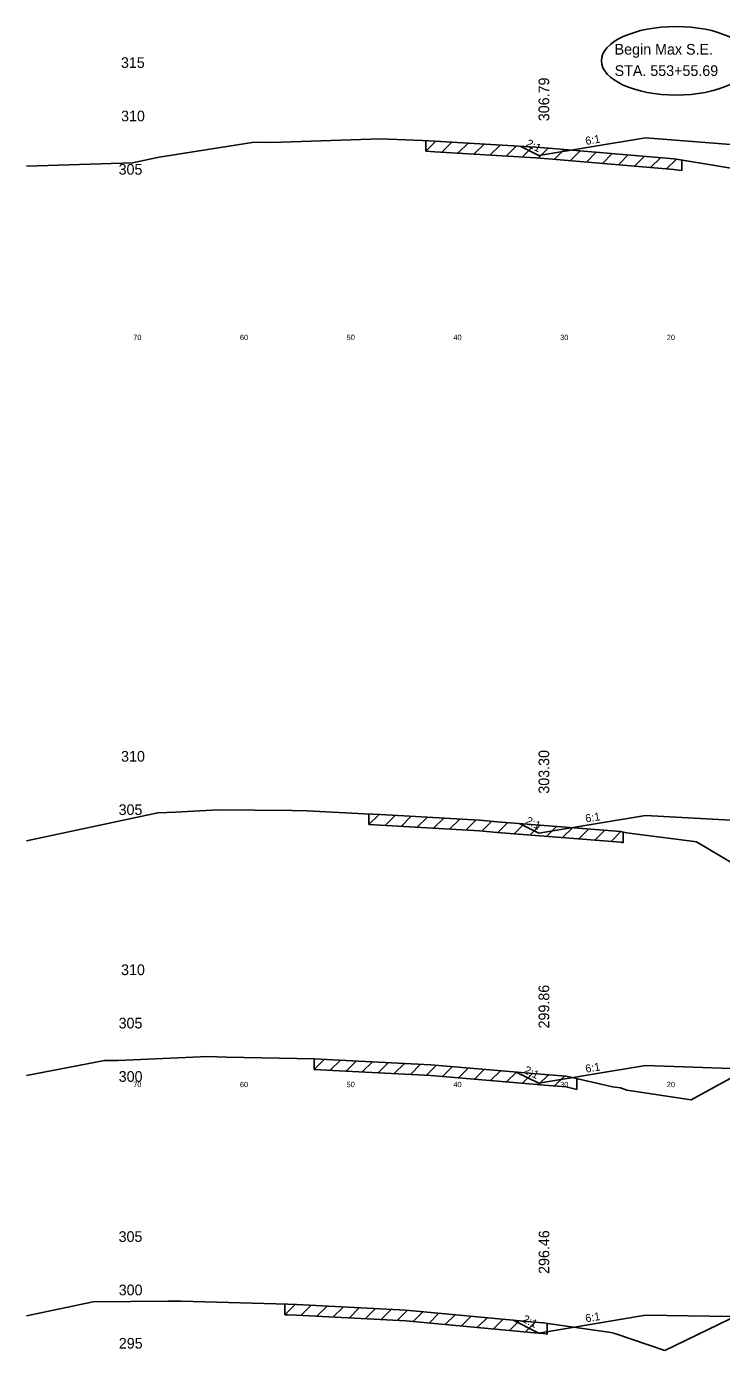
# Model space of a CAD drawing. Extents: x 1000 to 1162, y 999 to 8520.
# Drawn here: x 1000 to 1065.1, y 7344.8 to 7468.9 of the extents above; entities that cross this region are included whole.
import ezdxf

# ---------------------------------------------------------------- set-up
doc = ezdxf.new("R2010")
doc.units = 0
for name, color, linetype in [('Level 11', 7, 'Continuous'), ('Level 20', 7, 'Continuous'), ('Level 32', 7, 'Continuous'), ('Level 33', 7, 'Continuous'), ('Level 56', 7, 'Continuous'), ('Level 6', 7, 'Continuous'), ('Level 60', 7, 'Continuous'), ('Level 61', 7, 'Continuous'), ('Level 7', 7, 'Continuous')]:
    doc.layers.add(name, color=color, linetype=linetype)

msp = doc.modelspace()

# ---------------------------------------------------------------- linework, layer by layer
at = {"layer": 'Level 20'}
msp.add_ellipse((1060.87, 7465.67), major_axis=(7, 0), ratio=0.458988, dxfattribs=at)
at = {"layer": 'Level 6'}
for p, q in [((1058, 7458.46), (1066, 7457.84)), ((1058, 7394.97), (1066, 7394.51)), ((1058, 7371.53), (1066, 7371.24)), ((1058, 7348.13), (1066, 7348.01))]:
    msp.add_line(p, q, dxfattribs=at)
at = {"layer": 'Level 60'}
for p, q in [((1012.43, 7456.65), (1021.15, 7458.01)), ((1021.15, 7458.01), (1021.81, 7458.04)), ((1021.81, 7458.04), (1022.93, 7458.03)), ((1022.93, 7458.03), (1033.2, 7458.36)), ((1033.2, 7458.36), (1033.93, 7458.32)), ((1033.93, 7458.32), (1037.11, 7458.21)), ((1037.11, 7458.21), (1038.27, 7458.14)), ((1038.27, 7458.14), (1047.73, 7457.57)), ((1047.73, 7457.57), (1048.9, 7457.47)), ((1048.9, 7457.47), (1060.65, 7456.49)), ((1009.92, 7456.12), (1012.43, 7456.65)), ((1060.65, 7456.49), (1061.1, 7456.43)), ((1061.1, 7456.43), (1067.89, 7455.29)), ((1000, 7455.81), (1009.92, 7456.12)), ((1013.96, 7395.28), (1017.94, 7395.49)), ((1017.94, 7395.49), (1024.86, 7395.43)), ((1024.86, 7395.43), (1026.3, 7395.4)), ((1026.3, 7395.4), (1031.68, 7395.12)), ((1000, 7392.58), (1012.31, 7395.21)), ((1012.31, 7395.21), (1013.96, 7395.28)), ((1031.68, 7395.12), (1033.16, 7395.05)), ((1033.16, 7395.05), (1042.45, 7394.51)), ((1042.45, 7394.51), (1044.09, 7394.37)), ((1044.09, 7394.37), (1055.69, 7393.45)), ((1055.69, 7393.45), (1056.23, 7393.33)), ((1056.23, 7393.33), (1062.1, 7392.58)), ((1062.1, 7392.58), (1062.79, 7392.48)), ((1062.79, 7392.48), (1066.26, 7390.42)), ((1062.27, 7368.32), (1071.04, 7373.12)), ((1000, 7370.6), (1007.31, 7371.99)), ((1007.31, 7371.99), (1008.59, 7372.01)), ((1008.59, 7372.01), (1016.98, 7372.37)), ((1016.98, 7372.37), (1018.73, 7372.32)), ((1018.73, 7372.32), (1027, 7372.16)), ((1027, 7372.16), (1028.72, 7372.07)), ((1028.72, 7372.07), (1037.89, 7371.59)), ((1037.89, 7371.59), (1048.95, 7370.67)), ((1048.95, 7370.67), (1050.56, 7370.52)), ((1050.56, 7370.52), (1054.92, 7369.54)), ((1054.92, 7369.54), (1055.67, 7369.43)), ((1055.67, 7369.43), (1056.26, 7369.22)), ((1056.26, 7369.22), (1062.27, 7368.32)), ((1006.25, 7349.38), (1013.3, 7349.45)), ((1013.3, 7349.45), (1013.71, 7349.46)), ((1013.71, 7349.46), (1014.48, 7349.46)), ((1014.48, 7349.46), (1024.5, 7349.17)), ((1000, 7348.07), (1006.25, 7349.38)), ((1024.5, 7349.17), (1025.31, 7349.13)), ((1025.31, 7349.13), (1035.54, 7348.59)), ((1035.54, 7348.59), (1047.6, 7347.49)), ((1059.81, 7344.82), (1069.27, 7349.42)), ((1047.6, 7347.49), (1048.43, 7347.42)), ((1048.43, 7347.42), (1048.85, 7347.36)), ((1048.85, 7347.36), (1054.76, 7346.51)), ((1054.76, 7346.51), (1055.12, 7346.43)), ((1055.12, 7346.43), (1059.81, 7344.82))]:
    msp.add_line(p, q, dxfattribs=at)
at = {"layer": 'Level 61'}
for p, q in [((1037.42, 7458.19), (1037.42, 7457.19)), ((1038.36, 7458.14), (1037.42, 7457.19)), ((1039.87, 7458.05), (1038.92, 7457.1)), ((1041.37, 7457.96), (1040.42, 7457.01)), ((1042.87, 7457.86), (1041.93, 7456.92)), ((1044.38, 7457.77), (1043.43, 7456.83)), ((1045.88, 7457.68), (1044.94, 7456.74)), ((1047.39, 7457.59), (1046.44, 7456.65)), ((1048.87, 7457.48), (1047.95, 7456.55)), ((1037.42, 7457.19), (1038.27, 7457.14)), ((1038.27, 7457.14), (1047.73, 7456.57)), ((1047.73, 7456.57), (1048.9, 7456.47)), ((1048.9, 7456.47), (1060.65, 7455.49)), ((1050.38, 7457.35), (1049.45, 7456.43)), ((1051.88, 7457.22), (1050.95, 7456.3)), ((1053.38, 7457.1), (1052.46, 7456.18)), ((1054.89, 7456.97), (1053.96, 7456.05)), ((1056.39, 7456.85), (1055.47, 7455.92)), ((1057.9, 7456.72), (1056.97, 7455.8)), ((1059.4, 7456.59), (1058.48, 7455.67)), ((1060.9, 7456.46), (1059.98, 7455.55)), ((1061.4, 7455.38), (1061.4, 7456.38)), ((1060.65, 7455.49), (1061.1, 7455.43)), ((1061.1, 7455.43), (1061.4, 7455.38)), ((1032.08, 7395.1), (1032.08, 7394.1)), ((1033.04, 7395.05), (1032.08, 7394.1)), ((1034.55, 7394.97), (1033.6, 7394.02)), ((1036.06, 7394.88), (1035.11, 7393.93)), ((1037.57, 7394.79), (1036.62, 7393.85)), ((1039.09, 7394.7), (1038.13, 7393.76)), ((1040.6, 7394.62), (1039.64, 7393.67)), ((1042.11, 7394.53), (1041.16, 7393.59)), ((1043.6, 7394.41), (1042.67, 7393.49)), ((1045.11, 7394.29), (1044.18, 7393.37)), ((1046.63, 7394.17), (1045.69, 7393.25)), ((1032.08, 7394.1), (1033.16, 7394.05)), ((1033.16, 7394.05), (1042.45, 7393.51)), ((1042.45, 7393.51), (1044.09, 7393.37)), ((1044.09, 7393.37), (1055.69, 7392.45)), ((1048.14, 7394.05), (1047.21, 7393.13)), ((1049.65, 7393.93), (1048.72, 7393)), ((1051.16, 7393.81), (1050.23, 7392.88)), ((1052.68, 7393.69), (1051.74, 7392.76)), ((1054.19, 7393.57), (1053.26, 7392.64)), ((1055.7, 7393.45), (1054.77, 7392.52)), ((1055.9, 7392.4), (1055.9, 7393.4)), ((1055.69, 7392.45), (1055.9, 7392.4)), ((1026.95, 7372.16), (1026.95, 7371.16)), ((1027.91, 7372.12), (1026.95, 7371.16)), ((1029.41, 7372.04), (1028.45, 7371.09)), ((1030.91, 7371.96), (1029.96, 7371.01)), ((1032.41, 7371.88), (1031.46, 7370.93)), ((1033.91, 7371.8), (1032.96, 7370.85)), ((1026.95, 7371.16), (1027, 7371.16)), ((1027, 7371.16), (1028.72, 7371.07)), ((1028.72, 7371.07), (1037.89, 7370.59)), ((1035.41, 7371.72), (1034.46, 7370.77)), ((1036.92, 7371.64), (1035.97, 7370.69)), ((1038.4, 7371.54), (1037.47, 7370.61)), ((1037.89, 7370.59), (1048.95, 7369.67)), ((1039.89, 7371.42), (1038.97, 7370.5)), ((1041.4, 7371.29), (1040.47, 7370.37)), ((1042.9, 7371.17), (1041.97, 7370.25)), ((1044.4, 7371.04), (1043.48, 7370.12)), ((1045.9, 7370.92), (1044.98, 7370)), ((1047.41, 7370.79), (1046.48, 7369.87)), ((1048.91, 7370.67), (1047.98, 7369.75)), ((1048.95, 7369.67), (1050.56, 7369.52)), ((1050.4, 7370.53), (1049.49, 7369.62)), ((1050.56, 7369.52), (1051.56, 7369.29)), ((1051.56, 7369.29), (1051.56, 7370.29)), ((1024.22, 7349.17), (1024.22, 7348.17)), ((1025.18, 7349.14), (1024.22, 7348.17)), ((1026.67, 7349.06), (1025.72, 7348.11)), ((1028.17, 7348.98), (1027.22, 7348.03)), ((1029.68, 7348.9), (1028.72, 7347.95)), ((1031.18, 7348.82), (1030.23, 7347.87)), ((1032.68, 7348.74), (1031.73, 7347.79)), ((1034.18, 7348.67), (1033.23, 7347.72)), ((1035.68, 7348.58), (1034.73, 7347.64)), ((1037.15, 7348.45), (1036.24, 7347.53)), ((1038.65, 7348.31), (1037.74, 7347.39)), ((1024.22, 7348.17), (1024.5, 7348.17)), ((1024.5, 7348.17), (1025.31, 7348.13)), ((1025.31, 7348.13), (1035.54, 7347.59)), ((1035.54, 7347.59), (1047.6, 7346.49)), ((1040.16, 7348.17), (1039.24, 7347.25)), ((1041.66, 7348.03), (1040.74, 7347.12)), ((1043.16, 7347.89), (1042.24, 7346.98)), ((1044.66, 7347.76), (1043.75, 7346.84)), ((1046.17, 7347.62), (1045.25, 7346.7)), ((1047.67, 7347.48), (1046.75, 7346.56)), ((1048.78, 7346.37), (1048.78, 7347.37)), ((1047.6, 7346.49), (1048.43, 7346.42)), ((1048.43, 7346.42), (1048.78, 7346.37))]:
    msp.add_line(p, q, dxfattribs=at)
at = {"layer": 'Level 7'}
for p, q in [((1046.26, 7457.66), (1048, 7456.79)), ((1048, 7456.79), (1058, 7458.46)), ((1046.19, 7394.21), (1048, 7393.3)), ((1048, 7393.3), (1058, 7394.97)), ((1045.87, 7370.92), (1048, 7369.86)), ((1048, 7369.86), (1058, 7371.53)), ((1045.59, 7347.67), (1048, 7346.46)), ((1048, 7346.46), (1058, 7348.13))]:
    msp.add_line(p, q, dxfattribs=at)

# ---------------------------------------------------------------- texts
at = {"layer": 'Level 11'}
for s, p in [(' 315', (1008.48, 7465)), (' 310', (1008.49, 7460)), (' 305', (1008.26, 7455)), (' 310', (1008.49, 7400)), (' 305', (1008.26, 7395)), (' 310', (1008.49, 7380)), (' 305', (1008.26, 7375)), (' 300', (1008.27, 7370)), (' 305', (1008.26, 7355)), (' 300', (1008.27, 7350)), (' 295', (1008.28, 7345))]:
    msp.add_text(s, height=1, dxfattribs=at).set_placement(p)
at = {"layer": 'Level 20'}
for s, p in [('Begin Max S.E.', (1055.11, 7466.25)), ('STA. 553+55.69', (1055.11, 7464.25))]:
    msp.add_text(s, height=1, dxfattribs=at).set_placement(p)
at = {"layer": 'Level 32'}
for s, rotation, p in [('6:1', 9.4623, (1052.43, 7457.78)), ('2:1', 333.435, (1046.74, 7457.7)), ('2:1', 333.435, (1046.7, 7394.23)), ('6:1', 9.4623, (1052.43, 7394.29)), ('6:1', 9.4623, (1052.43, 7370.85)), ('2:1', 333.435, (1046.54, 7370.87)), ('6:1', 9.4623, (1052.43, 7347.46)), ('2:1', 333.435, (1046.4, 7347.54))]:
    msp.add_text(s, height=0.75, rotation=rotation, dxfattribs=at).set_placement(p)
at = {"layer": 'Level 33'}
for s, p in [('306.79', (1048.98, 7460.01)), ('303.30', (1048.98, 7397)), ('299.86', (1048.98, 7375)), ('296.46', (1048.99, 7352))]:
    msp.add_text(s, height=1, rotation=90, dxfattribs=at).set_placement(p)
at = {"layer": 'Level 56'}
for s, p in [('70', (1010, 7439.5)), ('60', (1020, 7439.5)), ('50', (1030, 7439.5)), ('40', (1040, 7439.5)), ('30', (1050, 7439.5)), ('20', (1060, 7439.5)), ('70', (1010, 7369.5)), ('60', (1020, 7369.5)), ('50', (1030, 7369.5)), ('40', (1040, 7369.5)), ('30', (1050, 7369.5)), ('20', (1060, 7369.5))]:
    msp.add_text(s, height=0.5, dxfattribs=at).set_placement(p)

doc.saveas('drawing.dxf')
